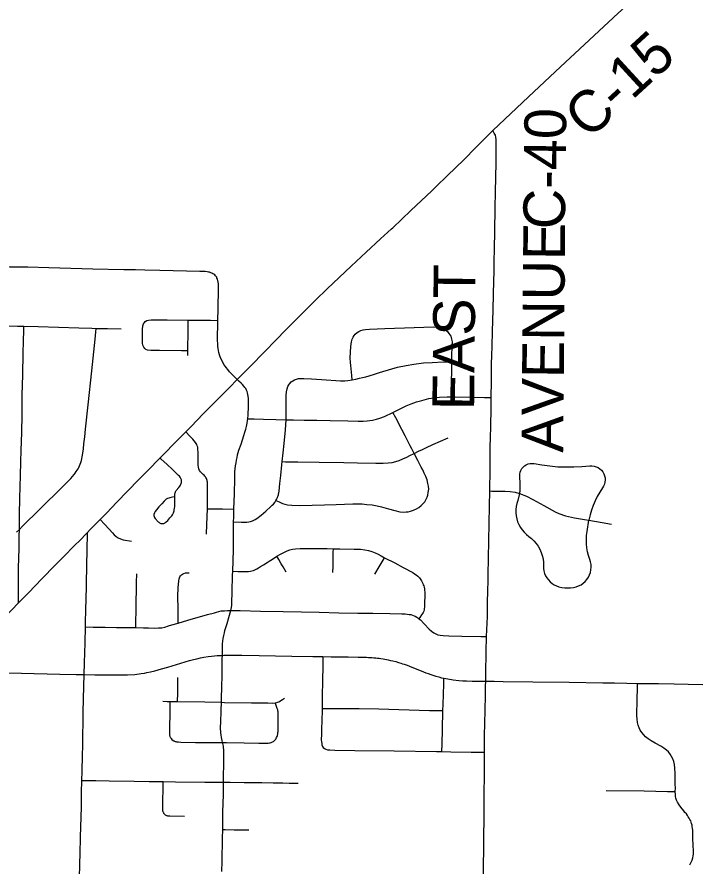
# Model space of a CAD drawing. Extents: x 1341221 to 1914484, y 79347 to 658398.
# Drawn here: x 1387868 to 1397403, y 622283 to 634169 of the extents above; entities that cross this region are included whole.
import ezdxf

# ---------------------------------------------------------------- set-up
doc = ezdxf.new("R2010")
doc.units = 0
for name, color, linetype in [('GM_X_Major_Lake_Text', 7, 'Continuous'), ('GM_X_State_Shield', 7, 'Continuous'), ('GM_X_US_Shield', 7, 'Continuous')]:
    doc.layers.add(name, color=color, linetype=linetype)

msp = doc.modelspace()

# ---------------------------------------------------------------- linework, layer by layer
at = {"layer": 'GM_X_State_Shield'}
for points in [[(1387119, 629864), (1387189, 629862), (1387275, 629859), (1387362, 629856), (1387423, 629854), (1387552, 629851), (1387877, 629842), (1387965, 629840), (1388165, 629834), (1388733, 629817), (1388915, 629812), (1388977, 629810), (1389079, 629808), (1389136, 629806), (1389328, 629802)], [(1390261, 629496), (1390173, 629496), (1389865, 629498), (1389744, 629500), (1389695, 629505), (1389674, 629514), (1389656, 629528), (1389642, 629546), (1389631, 629573), (1389626, 629603), (1389627, 629794), (1389631, 629843), (1389640, 629872), (1389652, 629892), (1389664, 629904), (1389688, 629919), (1389711, 629925), (1389748, 629928), (1389971, 629927), (1390266, 629925), (1390579, 629922), (1390681, 629921)], [(1390261, 629429), (1390261, 629496), (1390264, 629783), (1390265, 629815), (1390266, 629925)], [(1387863, 626958), (1387901, 626996), (1387943, 627039), (1388003, 627098), (1388130, 627223), (1388221, 627312), (1388470, 627560), (1388620, 627710), (1388645, 627737), (1388667, 627763), (1388684, 627784), (1388698, 627804), (1388711, 627823), (1388722, 627843), (1388733, 627862), (1388743, 627884), (1388753, 627909), (1388761, 627933), (1388770, 627961), (1388775, 627983), (1388781, 628010), (1388785, 628034), (1388797, 628121), (1388805, 628193), (1388816, 628292), (1388827, 628399), (1388863, 628740), (1388914, 629217), (1388944, 629482), (1388962, 629660), (1388973, 629763), (1388977, 629810)], [(1387887, 625965), (1387887, 626018), (1387888, 626456), (1387896, 626727), (1387899, 626904), (1387901, 626996), (1387902, 627100), (1387904, 627202), (1387908, 627431), (1387918, 627750), (1387922, 627942), (1387927, 628102), (1387935, 628351), (1387938, 628599), (1387942, 628875), (1387951, 629157), (1387955, 629464), (1387960, 629630), (1387964, 629784), (1387965, 629840)], [(1392562, 629089), (1392555, 629152), (1392545, 629245), (1392540, 629292), (1392536, 629334), (1392534, 629398), (1392537, 629475), (1392543, 629558), (1392553, 629621), (1392562, 629658), (1392574, 629688), (1392588, 629710), (1392605, 629729), (1392629, 629750), (1392655, 629768), (1392684, 629782), (1392715, 629791), (1392746, 629796), (1392804, 629800), (1393016, 629807), (1393431, 629821), (1393700, 629829), (1393751, 629828), (1393790, 629823), (1393820, 629814), (1393849, 629800), (1393875, 629782), (1393899, 629760), (1393915, 629740), (1393930, 629718), (1393940, 629699), (1393948, 629680), (1393953, 629660), (1393957, 629641), (1393959, 629620), (1393960, 629594)], [(1393946, 628851), (1393948, 628933), (1393951, 629044), (1393956, 629232), (1393956, 629337), (1393956, 629365), (1393958, 629455), (1393959, 629529), (1393960, 629594)], [(1391637, 628528), (1391636, 628603), (1391636, 628685), (1391636, 628781), (1391636, 628828), (1391638, 628871), (1391643, 628923), (1391650, 628962), (1391661, 628994), (1391673, 629018), (1391688, 629040), (1391706, 629060), (1391728, 629076), (1391752, 629089), (1391783, 629100), (1391810, 629106), (1391843, 629108), (1391885, 629108), (1391991, 629101), (1392131, 629094), (1392399, 629077), (1392456, 629076), (1392500, 629079), (1392562, 629089), (1392610, 629098), (1392662, 629111), (1392705, 629121), (1392752, 629133), (1392858, 629165), (1392944, 629191), (1393116, 629245), (1393197, 629266), (1393316, 629291), (1393424, 629309), (1393558, 629325), (1393679, 629334), (1393833, 629340), (1393921, 629338), (1393956, 629337)], [(1391098, 628545), (1391187, 628542), (1391319, 628538), (1391493, 628532), (1391637, 628528), (1391740, 628527), (1391890, 628525), (1392068, 628524), (1392253, 628520), (1392501, 628513), (1392645, 628509), (1392713, 628510), (1392769, 628515), (1392845, 628525), (1392900, 628537), (1392949, 628551), (1393013, 628577), (1393132, 628631), (1393179, 628654), (1393232, 628681), (1393318, 628723), (1393389, 628754), (1393462, 628780), (1393536, 628802), (1393636, 628826), (1393706, 628837), (1393783, 628845), (1393892, 628851), (1393946, 628851), (1394001, 628852), (1394269, 628846), (1394416, 628844), (1394509, 628842)], [(1391493, 627400), (1391537, 627380), (1391583, 627358), (1391620, 627347), (1391657, 627339), (1391714, 627333), (1391817, 627330), (1392002, 627333), (1392175, 627339), (1392335, 627344), (1392572, 627353), (1392642, 627353), (1392701, 627351), (1392764, 627346), (1392840, 627338), (1392909, 627326), (1392972, 627311), (1393070, 627282), (1393158, 627258), (1393229, 627243), (1393277, 627236), (1393315, 627239), (1393347, 627243), (1393378, 627250), (1393420, 627265), (1393461, 627284), (1393494, 627304), (1393529, 627331), (1393557, 627358), (1393576, 627383), (1393593, 627410), (1393609, 627445), (1393619, 627476), (1393626, 627513), (1393632, 627558), (1393629, 627600), (1393621, 627640), (1393609, 627688), (1393591, 627738), (1393571, 627781), (1393549, 627828), (1393528, 627868), (1393479, 627960), (1393428, 628057), (1393396, 628121), (1393373, 628166), (1393304, 628303), (1393258, 628396), (1393170, 628559), (1393132, 628631)], [(1390901, 627100), (1391012, 627095), (1391036, 627095), (1391062, 627095), (1391087, 627097), (1391114, 627100), (1391139, 627107), (1391167, 627115), (1391186, 627123), (1391204, 627134), (1391224, 627148), (1391243, 627162), (1391268, 627181), (1391288, 627196), (1391351, 627251), (1391422, 627314), (1391442, 627333), (1391458, 627350), (1391477, 627373), (1391493, 627400), (1391502, 627415), (1391509, 627431), (1391517, 627448), (1391523, 627464), (1391528, 627481), (1391531, 627494), (1391534, 627507), (1391537, 627530), (1391550, 627640), (1391560, 627750), (1391576, 627898), (1391581, 627944), (1391595, 628068), (1391610, 628200), (1391625, 628387), (1391637, 628528)], [(1390522, 626928), (1390524, 627066), (1390533, 627285), (1390535, 627375), (1390536, 627495), (1390537, 627605), (1390536, 627636), (1390534, 627655), (1390532, 627669), (1390530, 627681), (1390524, 627695), (1390519, 627708), (1390513, 627720), (1390506, 627731), (1390497, 627742), (1390487, 627754), (1390474, 627766), (1390439, 627801), (1390424, 627821), (1390414, 627842), (1390408, 627865), (1390404, 627895), (1390404, 628004), (1390403, 628074), (1390402, 628120), (1390398, 628146), (1390392, 628166), (1390384, 628185), (1390366, 628212), (1390349, 628235), (1390329, 628258), (1390308, 628281), (1390289, 628301), (1390232, 628363)], [(1393428, 628057), (1393491, 628090), (1393546, 628116), (1393601, 628143), (1393688, 628183), (1393907, 628279)], [(1390076, 627449), (1390047, 627445), (1390027, 627442), (1390008, 627438), (1389992, 627434), (1389974, 627428), (1389957, 627417), (1389943, 627404), (1389927, 627389), (1389894, 627353), (1389856, 627310), (1389822, 627271), (1389801, 627245), (1389792, 627226), (1389786, 627206), (1389785, 627191), (1389787, 627176), (1389793, 627162), (1389801, 627150), (1389845, 627102), (1389854, 627095), (1389862, 627089), (1389872, 627084), (1389881, 627080), (1389889, 627079), (1389896, 627077), (1389904, 627077), (1389911, 627077), (1389918, 627079), (1389925, 627080), (1389932, 627083), (1389938, 627086), (1389949, 627093), (1389955, 627099), (1389978, 627121), (1390010, 627155), (1390024, 627171), (1390035, 627185), (1390044, 627198), (1390050, 627208), (1390057, 627225), (1390062, 627239), (1390067, 627257), (1390070, 627271), (1390074, 627291), (1390076, 627310), (1390078, 627342), (1390079, 627368), (1390079, 627406), (1390078, 627445), (1390078, 627483), (1390082, 627506), (1390088, 627522), (1390097, 627538), (1390132, 627583), (1390146, 627601), (1390155, 627615), (1390162, 627628), (1390167, 627640), (1390170, 627651), (1390171, 627661), (1390172, 627669), (1390171, 627675), (1390170, 627684), (1390169, 627689), (1390166, 627699), (1390162, 627709), (1390151, 627727), (1390141, 627739), (1390129, 627752), (1390041, 627837), (1389971, 627903), (1389883, 627984), (1389871, 627995)], [(1391581, 627944), (1391626, 627943), (1391713, 627941), (1391799, 627939), (1392100, 627936), (1392446, 627932), (1392636, 627929), (1392891, 627921), (1392993, 627921), (1393063, 627925), (1393120, 627933), (1393170, 627944), (1393219, 627959), (1393272, 627981), (1393324, 628005), (1393369, 628028), (1393428, 628057)], [(1394906, 627497), (1394911, 627529), (1394912, 627537), (1394915, 627584), (1394915, 627632), (1394908, 627741), (1394909, 627769), (1394914, 627796), (1394924, 627822), (1394937, 627846), (1394955, 627868), (1394976, 627886), (1394999, 627901), (1395025, 627911), (1395052, 627917), (1395080, 627919), (1395107, 627916), (1395217, 627897), (1395329, 627883), (1395440, 627873), (1395552, 627869), (1395664, 627869), (1395776, 627874), (1395887, 627883), (1395917, 627884), (1395947, 627880), (1395976, 627872), (1396003, 627860), (1396028, 627843), (1396050, 627823), (1396069, 627800), (1396084, 627774), (1396094, 627746), (1396101, 627717), (1396103, 627687), (1396100, 627657), (1396093, 627628), (1396082, 627601), (1396066, 627575), (1396027, 627517), (1395992, 627457), (1395961, 627395), (1395934, 627330), (1395911, 627264), (1395893, 627197), (1395873, 627125)], [(1394487, 627533), (1394516, 627532), (1394705, 627531), (1394771, 627528), (1394842, 627516), (1394906, 627497), (1395003, 627461), (1395092, 627415), (1395244, 627332), (1395402, 627240), (1395454, 627218), (1395550, 627186), (1395674, 627159), (1395814, 627136), (1395873, 627125), (1396059, 627093), (1396194, 627068)], [(1394906, 627497), (1394880, 627400), (1394866, 627358), (1394857, 627316), (1394853, 627273), (1394853, 627229), (1394857, 627186), (1394865, 627144), (1394878, 627102), (1394895, 627062), (1394916, 627024), (1394940, 626988), (1394968, 626955), (1395000, 626925), (1395034, 626898), (1395072, 626869), (1395106, 626836), (1395138, 626799), (1395165, 626760), (1395189, 626718), (1395208, 626673), (1395223, 626628), (1395233, 626581), (1395239, 626533), (1395240, 626485), (1395241, 626449), (1395246, 626414), (1395255, 626380), (1395269, 626347), (1395287, 626316), (1395308, 626288), (1395332, 626262), (1395359, 626239), (1395389, 626220), (1395421, 626204), (1395455, 626193), (1395495, 626184), (1395537, 626178), (1395578, 626176), (1395620, 626177), (1395661, 626182), (1395697, 626190), (1395732, 626203), (1395765, 626220), (1395796, 626241), (1395823, 626266), (1395847, 626294), (1395868, 626325), (1395884, 626358), (1395896, 626393), (1395904, 626429), (1395907, 626466), (1395905, 626503), (1395899, 626539), (1395888, 626575), (1395870, 626628), (1395856, 626683), (1395846, 626739), (1395841, 626795), (1395840, 626851), (1395843, 626908), (1395850, 626964), (1395873, 627125)], [(1390533, 627285), (1390623, 627284), (1390743, 627283), (1390906, 627280)], [(1389032, 627133), (1389092, 627070), (1389158, 627000), (1389203, 626946), (1389229, 626919), (1389258, 626895), (1389285, 626878), (1389319, 626862), (1389356, 626851), (1389469, 626830)], [(1390888, 626411), (1390961, 626407), (1391011, 626404), (1391049, 626404), (1391083, 626404), (1391110, 626406), (1391135, 626409), (1391158, 626415), (1391180, 626422), (1391205, 626433), (1391228, 626445), (1391251, 626459), (1391279, 626475), (1391317, 626499), (1391372, 626534), (1391413, 626559), (1391415, 626560), (1391508, 626619), (1391557, 626647), (1391604, 626673), (1391649, 626696), (1391687, 626710), (1391725, 626719), (1391766, 626725), (1391832, 626728), (1391915, 626729), (1392044, 626728), (1392211, 626726), (1392298, 626725), (1392389, 626723), (1392589, 626720), (1392678, 626717), (1392740, 626710), (1392790, 626701), (1392838, 626687), (1392885, 626668), (1392923, 626648), (1392967, 626624), (1393014, 626599), (1393157, 626525), (1393274, 626463), (1393409, 626390), (1393435, 626374), (1393457, 626360), (1393481, 626340), (1393502, 626318), (1393513, 626304), (1393524, 626288), (1393532, 626274), (1393542, 626255), (1393550, 626238), (1393557, 626221), (1393562, 626205), (1393567, 626185), (1393572, 626165), (1393575, 626142), (1393577, 626120), (1393578, 626099), (1393577, 626043), (1393575, 625989), (1393572, 625912), (1393570, 625883), (1393568, 625870), (1393564, 625852), (1393557, 625834), (1393547, 625819), (1393532, 625797), (1393509, 625764), (1393495, 625745)], [(1392292, 626394), (1392293, 626481), (1392295, 626556), (1392297, 626676), (1392298, 626725)], [(1391637, 626398), (1391594, 626470), (1391568, 626513), (1391534, 626574), (1391508, 626619)], [(1392879, 626368), (1392939, 626469), (1393007, 626588), (1393014, 626599)], [(1389531, 625620), (1389532, 625696), (1389535, 625863), (1389537, 626004), (1389540, 626129), (1389542, 626252), (1389545, 626375)], [(1390126, 625684), (1390124, 625778), (1390123, 625877), (1390121, 626062), (1390125, 626177), (1390133, 626273), (1390138, 626304), (1390146, 626329), (1390156, 626345), (1390169, 626359), (1390184, 626370), (1390202, 626379), (1390226, 626386), (1390252, 626389), (1390277, 626388)], [(1388827, 625631), (1388936, 625628), (1389100, 625625), (1389263, 625623), (1389452, 625621), (1389531, 625620), (1389638, 625618), (1389707, 625616), (1389788, 625614), (1389848, 625615), (1389894, 625619), (1389939, 625628), (1389990, 625644), (1390038, 625658), (1390126, 625684), (1390262, 625726), (1390533, 625802), (1390631, 625828), (1390663, 625837), (1390694, 625845), (1390728, 625853), (1390773, 625856), (1390815, 625859), (1390862, 625860), (1390881, 625860), (1390904, 625860), (1390947, 625860), (1390994, 625859), (1391277, 625850), (1391596, 625844), (1391852, 625841), (1392100, 625835), (1392374, 625829), (1392638, 625823), (1392851, 625821), (1393088, 625819), (1393258, 625815), (1393301, 625813), (1393332, 625810), (1393357, 625806), (1393382, 625802), (1393407, 625794), (1393429, 625787), (1393445, 625780), (1393466, 625767), (1393479, 625758), (1393495, 625745), (1393516, 625727), (1393571, 625671), (1393641, 625599), (1393670, 625572), (1393702, 625549), (1393731, 625533), (1393762, 625521), (1393794, 625513), (1393833, 625508), (1393916, 625503), (1394097, 625500), (1394364, 625496), (1394444, 625495)], [(1392151, 625215), (1392150, 625150), (1392148, 625060), (1392144, 624897), (1392141, 624636), (1392140, 624490), (1392139, 624459), (1392135, 624318), (1392132, 624199), (1392131, 624130), (1392129, 624051), (1392131, 624022), (1392134, 623997), (1392136, 623981), (1392145, 623958), (1392156, 623940), (1392173, 623927), (1392191, 623918), (1392214, 623911), (1392247, 623907), (1392316, 623906), (1392597, 623902), (1393147, 623896), (1393742, 623887), (1393817, 623885), (1393940, 623882), (1394228, 623876), (1394317, 623876), (1394414, 623876)], [(1390117, 624585), (1390117, 624625), (1390118, 624664), (1390119, 624718), (1390120, 624781), (1390120, 624834), (1390120, 624879), (1390120, 624924)], [(1393817, 623885), (1393820, 623993), (1393825, 624196), (1393832, 624458), (1393834, 624543), (1393838, 624684), (1393842, 624834), (1393844, 624913)], [(1397289, 622299), (1397309, 622337), (1397322, 622365), (1397330, 622396), (1397335, 622427), (1397338, 622450), (1397338, 622489), (1397335, 622576), (1397333, 622670), (1397331, 622747), (1397330, 622779), (1397327, 622811), (1397323, 622833), (1397320, 622855), (1397314, 622876), (1397307, 622898), (1397301, 622914), (1397291, 622933), (1397279, 622954), (1397267, 622971), (1397254, 622992), (1397240, 623011), (1397221, 623034), (1397205, 623055), (1397162, 623107), (1397138, 623140), (1397116, 623175), (1397102, 623204), (1397093, 623234), (1397088, 623260), (1397086, 623286), (1397085, 623325), (1397086, 623371), (1397085, 623429), (1397084, 623576), (1397081, 623653), (1397075, 623703), (1397064, 623747), (1397051, 623783), (1397034, 623817), (1397013, 623849), (1396988, 623879), (1396961, 623905), (1396926, 623933), (1396883, 623961), (1396803, 624002), (1396747, 624033), (1396705, 624061), (1396670, 624090), (1396643, 624117), (1396615, 624152), (1396595, 624184), (1396578, 624219), (1396565, 624255), (1396556, 624292), (1396550, 624337), (1396548, 624388), (1396552, 624612), (1396555, 624778), (1396556, 624839)], [(1389912, 624590), (1389970, 624587), (1390007, 624586), (1390066, 624585), (1390117, 624585), (1390496, 624579), (1390729, 624575), (1390775, 624574), (1391153, 624568), (1391378, 624565), (1391447, 624564), (1391482, 624567), (1391504, 624571), (1391516, 624576), (1391532, 624582), (1391546, 624589), (1391584, 624612), (1391612, 624632)], [(1390007, 624586), (1390007, 624541), (1390007, 624403), (1390005, 624241), (1390004, 624172), (1390003, 624133), (1390004, 624124), (1390005, 624113), (1390007, 624105), (1390009, 624097), (1390013, 624088), (1390016, 624081), (1390020, 624074), (1390025, 624067), (1390035, 624054), (1390053, 624041), (1390059, 624037), (1390067, 624033), (1390075, 624029), (1390084, 624026), (1390093, 624024), (1390102, 624022), (1390115, 624020), (1390128, 624019), (1390160, 624017), (1390365, 624014), (1390595, 624013), (1390747, 624012), (1390800, 624011), (1391049, 624006), (1391254, 624002), (1391369, 624002), (1391385, 624003), (1391401, 624005), (1391414, 624008), (1391426, 624011), (1391438, 624016), (1391447, 624019), (1391457, 624026), (1391465, 624031), (1391472, 624038), (1391479, 624044), (1391485, 624052), (1391491, 624060), (1391497, 624070), (1391503, 624082), (1391509, 624094), (1391513, 624105), (1391517, 624117), (1391519, 624130), (1391521, 624142), (1391522, 624154), (1391523, 624168), (1391525, 624399), (1391524, 624421), (1391523, 624439), (1391521, 624455), (1391519, 624469), (1391512, 624490), (1391496, 624531), (1391482, 624567)], [(1392140, 624490), (1392248, 624490), (1392390, 624488), (1392660, 624486), (1392935, 624481), (1393075, 624477), (1393501, 624466), (1393644, 624462), (1393747, 624460), (1393832, 624458)], [(1388775, 623479), (1388813, 623479), (1388973, 623478), (1389159, 623476), (1389510, 623470), (1389719, 623467), (1389878, 623464), (1389915, 623464), (1390088, 623462), (1390498, 623456), (1390760, 623457), (1390853, 623458), (1391047, 623453), (1391173, 623452), (1391297, 623450), (1391456, 623447), (1391590, 623445), (1391679, 623443), (1391805, 623442)], [(1390212, 622978), (1390008, 622979), (1389993, 622980), (1389982, 622982), (1389972, 622984), (1389964, 622987), (1389955, 622992), (1389947, 622996), (1389939, 623003), (1389933, 623009), (1389926, 623017), (1389922, 623025), (1389917, 623034), (1389914, 623043), (1389912, 623053), (1389910, 623063), (1389909, 623077), (1389908, 623091), (1389910, 623194), (1389913, 623365), (1389914, 623423), (1389915, 623464)], [(1396115, 623341), (1396651, 623333), (1396977, 623327), (1397085, 623325)], [(1390748, 622794), (1390783, 622793), (1390909, 622790), (1391033, 622789), (1391114, 622789)]]:
    msp.add_lwpolyline(points, dxfattribs=at)
at = {"layer": 'GM_X_US_Shield'}
for points in [[(1393736, 631794), (1393893, 631944), (1394127, 632172), (1394288, 632336), (1394529, 632578), (1395031, 633051), (1395480, 633470), (1396285, 634220), (1397196, 635053), (1397492, 635329), (1397678, 635502), (1398215, 636004), (1398503, 636277), (1399323, 637058), (1399817, 637536), (1399903, 637620), (1399983, 637688), (1400042, 637736), (1400096, 637775), (1400155, 637809), (1400194, 637830), (1400233, 637849)], [(1394547, 630606), (1394549, 630738), (1394552, 630930), (1394558, 631160), (1394565, 631501), (1394570, 631715), (1394577, 632130), (1394577, 632452), (1394572, 632485), (1394566, 632516), (1394551, 632544), (1394529, 632578)], [(1393112, 631203), (1393128, 631218), (1393384, 631459), (1393676, 631736), (1393736, 631794)], [(1391926, 630085), (1392047, 630206), (1392209, 630361), (1392546, 630680), (1392756, 630875), (1392958, 631063), (1393112, 631203)], [(1389364, 630630), (1388929, 630639), (1388312, 630659), (1388018, 630666), (1387767, 630668), (1387514, 630670), (1387411, 630672), (1387151, 630677)], [(1390681, 629921), (1390683, 630081), (1390684, 630114), (1390684, 630141), (1390688, 630313), (1390689, 630357), (1390688, 630398), (1390687, 630432), (1390683, 630458), (1390679, 630479), (1390674, 630496), (1390668, 630512), (1390664, 630525), (1390657, 630535), (1390649, 630546), (1390637, 630557), (1390625, 630567), (1390612, 630575), (1390597, 630583), (1390583, 630588), (1390564, 630594), (1390550, 630598), (1390531, 630601), (1390504, 630604), (1390478, 630605), (1390453, 630606), (1390426, 630606), (1389869, 630620), (1389660, 630624), (1389529, 630627), (1389375, 630630), (1389364, 630630)], [(1394509, 628842), (1394510, 629070), (1394514, 629314), (1394516, 629428), (1394519, 629562), (1394525, 629766), (1394537, 630071), (1394541, 630290), (1394544, 630472), (1394547, 630606)], [(1388841, 626938), (1388855, 626952), (1388894, 626992), (1388964, 627064), (1389032, 627133), (1389125, 627228), (1389263, 627371), (1389574, 627692), (1389695, 627814), (1389871, 627995), (1390133, 628265), (1390232, 628363), (1390305, 628436), (1390475, 628611), (1390727, 628865), (1390843, 628984), (1390951, 629094), (1391155, 629301), (1391313, 629462), (1391515, 629667), (1391609, 629764), (1391926, 630085)], [(1390951, 629094), (1390923, 629120), (1390893, 629151), (1390845, 629202), (1390818, 629233), (1390798, 629260), (1390785, 629278), (1390766, 629305), (1390745, 629344), (1390723, 629387), (1390712, 629413), (1390702, 629440), (1390694, 629472), (1390689, 629500), (1390684, 629530), (1390681, 629561), (1390679, 629596), (1390677, 629636), (1390681, 629921)], [(1390734, 622205), (1390741, 622346), (1390746, 622672), (1390748, 622794), (1390751, 623036), (1390758, 623286), (1390760, 623457), (1390761, 623585), (1390764, 623663), (1390763, 623731), (1390763, 623793), (1390763, 623842), (1390763, 623880), (1390762, 623913), (1390760, 623937), (1390757, 623959), (1390750, 623997), (1390747, 624012), (1390741, 624039), (1390732, 624084), (1390725, 624121), (1390723, 624141), (1390721, 624165), (1390719, 624198), (1390718, 624233), (1390720, 624293), (1390725, 624461), (1390729, 624575), (1390730, 624609), (1390738, 624810), (1390739, 624931), (1390741, 625052), (1390741, 625117), (1390742, 625185), (1390743, 625232), (1390745, 625345), (1390747, 625393), (1390750, 625430), (1390755, 625469), (1390763, 625511), (1390771, 625546), (1390780, 625578), (1390810, 625678), (1390835, 625762), (1390854, 625825), (1390862, 625860), (1390870, 625902), (1390874, 625934), (1390877, 625964), (1390880, 626124), (1390886, 626351), (1390888, 626411), (1390897, 626706), (1390901, 626994), (1390901, 627100), (1390903, 627165), (1390904, 627227), (1390906, 627280), (1390911, 627495), (1390916, 627710), (1390918, 627757), (1390920, 627799), (1390924, 627842), (1390929, 627887), (1390935, 627928), (1390941, 627963), (1390949, 628001), (1390957, 628037), (1390966, 628071), (1390976, 628104), (1391005, 628189), (1391025, 628249), (1391045, 628310), (1391060, 628358), (1391071, 628398), (1391080, 628436), (1391089, 628482), (1391094, 628518), (1391098, 628545), (1391103, 628598), (1391105, 628638), (1391108, 628680), (1391111, 628743), (1391110, 628794), (1391109, 628829), (1391105, 628860), (1391101, 628885), (1391095, 628905), (1391089, 628926), (1391081, 628946), (1391070, 628966), (1391059, 628984), (1391046, 629001), (1391027, 629023), (1391007, 629044), (1390975, 629072), (1390951, 629094)], [(1394494, 628168), (1394496, 628259), (1394501, 628456), (1394505, 628674), (1394509, 628814), (1394509, 628842)], [(1394431, 624869), (1394432, 624975), (1394437, 625282), (1394444, 625495), (1394454, 625778), (1394458, 625983), (1394462, 626124), (1394465, 626284), (1394467, 626361), (1394472, 626591), (1394484, 627322), (1394487, 627533), (1394491, 627836), (1394491, 627977), (1394493, 628107), (1394494, 628168)], [(1386983, 625004), (1387031, 625065), (1387065, 625104), (1387106, 625148), (1387156, 625203), (1387231, 625282), (1387305, 625366), (1387399, 625465), (1387500, 625572), (1387600, 625678), (1387796, 625871), (1387887, 625965), (1388028, 626109), (1388215, 626302), (1388404, 626494), (1388539, 626630), (1388654, 626750), (1388769, 626865), (1388819, 626916), (1388841, 626938)], [(1388745, 622097), (1388749, 622321), (1388752, 622449), (1388756, 622689), (1388769, 623108), (1388772, 623314), (1388775, 623479), (1388778, 623612), (1388785, 623830), (1388788, 623970), (1388796, 624437), (1388804, 624802), (1388809, 624962), (1388813, 625127), (1388820, 625409), (1388827, 625631), (1388829, 625698), (1388832, 625863), (1388842, 626189), (1388842, 626279), (1388845, 626445), (1388850, 626758), (1388853, 626886), (1388855, 626952)], [(1387360, 624997), (1387932, 624981), (1388468, 624969), (1388697, 624965), (1388809, 624962), (1388958, 624961), (1389283, 624958), (1389357, 624958), (1389417, 624960), (1389518, 624966), (1389607, 624976), (1389652, 624983), (1389688, 624990), (1389737, 625000), (1389799, 625017), (1389892, 625043), (1389978, 625067), (1390284, 625160), (1390340, 625175), (1390384, 625185), (1390437, 625195), (1390485, 625205), (1390544, 625215), (1390593, 625221), (1390631, 625226), (1390670, 625229), (1390743, 625232), (1390766, 625233), (1390838, 625234), (1390914, 625234), (1391017, 625234), (1391259, 625229), (1391714, 625221), (1392008, 625218), (1392113, 625216), (1392151, 625215), (1392265, 625213), (1392507, 625209), (1392645, 625207), (1392706, 625206), (1392763, 625205), (1392790, 625204), (1392812, 625203), (1392837, 625201), (1392863, 625199), (1392891, 625196), (1392917, 625194), (1392941, 625191), (1392962, 625188), (1392994, 625183), (1393019, 625179), (1393043, 625174), (1393066, 625170), (1393099, 625162), (1393131, 625155), (1393170, 625144), (1393208, 625133), (1393241, 625123), (1393267, 625115), (1393291, 625108), (1393330, 625093), (1393364, 625081), (1393561, 625001), (1393592, 624988), (1393626, 624976), (1393660, 624965), (1393689, 624955), (1393733, 624941), (1393775, 624929), (1393813, 624919), (1393844, 624913), (1393900, 624902), (1393974, 624890), (1394054, 624881), (1394112, 624876), (1394161, 624874), (1394239, 624872), (1394304, 624870), (1394377, 624869), (1394431, 624869)], [(1394394, 621943), (1394405, 622557), (1394411, 623082), (1394410, 623242), (1394415, 623606), (1394414, 623862), (1394414, 623876), (1394415, 624099), (1394418, 624285), (1394422, 624457), (1394427, 624678), (1394429, 624801), (1394431, 624869)], [(1394431, 624869), (1394547, 624869), (1394677, 624867), (1395089, 624863), (1395601, 624856), (1396069, 624849), (1396127, 624848), (1396137, 624848)], [(1396137, 624848), (1396233, 624846), (1396405, 624843), (1396556, 624839), (1396700, 624838), (1396849, 624836), (1397069, 624833), (1397267, 624829), (1397469, 624825)]]:
    msp.add_lwpolyline(points, dxfattribs=at)

# ---------------------------------------------------------------- texts
at = {"layer": 'GM_X_Major_Lake_Text'}
for s, rotation, p in [('C-15', 42.5736, (1395872, 632440)), ('C-40', 89.3139, (1395540, 631195)), ('AVENUE', 89.4997, (1395515, 628068)), ('EAST', 89.4489, (1394268, 628661))]:
    msp.add_text(s, height=585, rotation=rotation, dxfattribs=at).set_placement(p)

doc.saveas('drawing.dxf')
